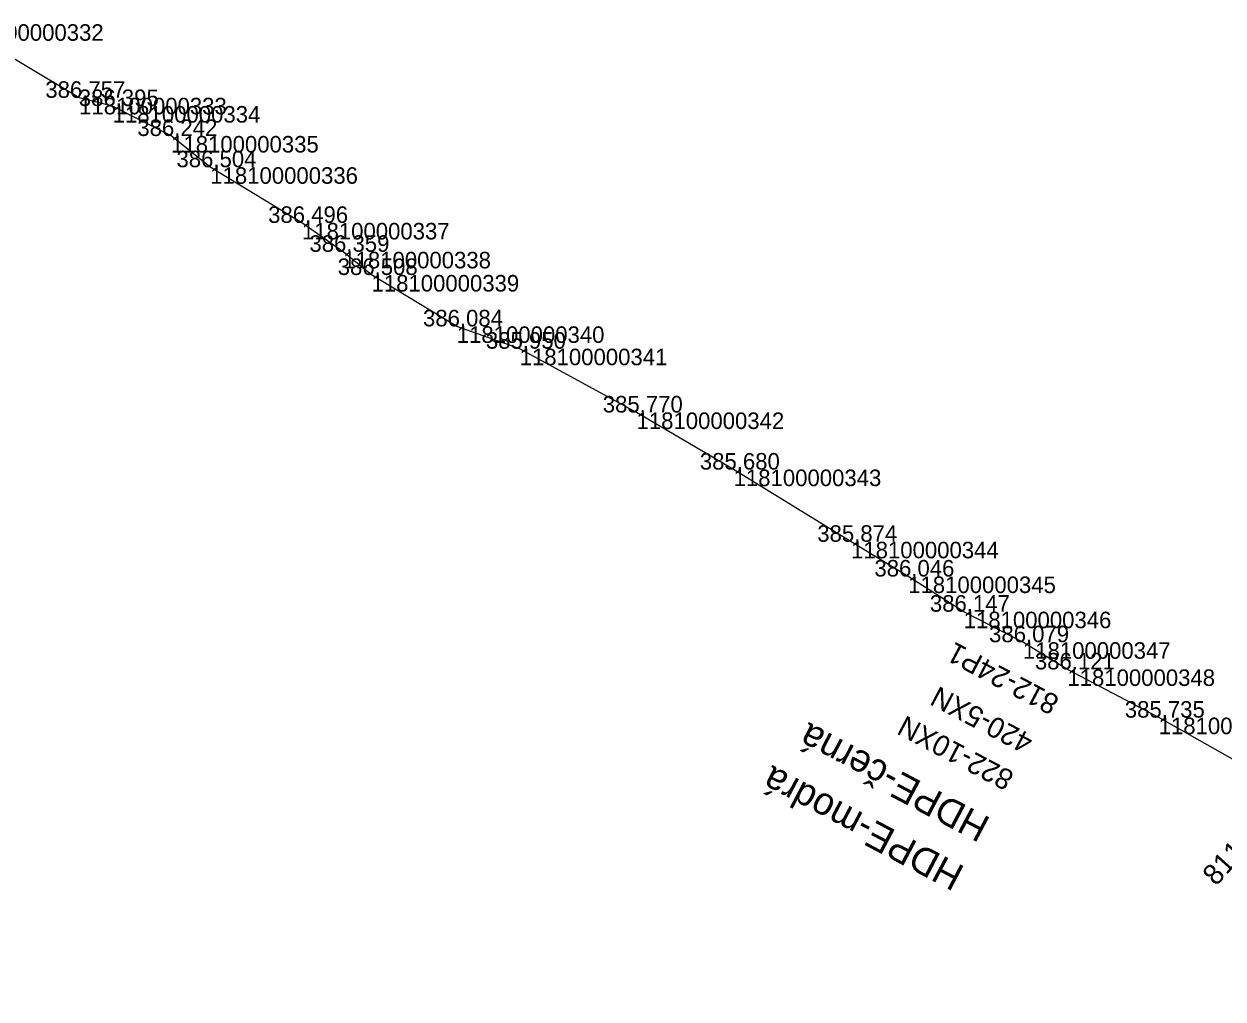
# Model space of a CAD drawing. Extents: x -724084 to -720954, y -948423 to -945131.
# Drawn here: x -721678.5 to -721591.6, y -947872.5 to -947801.8 of the extents above; entities that cross this region are included whole.
import ezdxf

# ---------------------------------------------------------------- set-up
doc = ezdxf.new("R2010")
doc.units = 0
for name, color, linetype in [('Vrstva 28', 7, 'Continuous'), ('Vrstva 31', 7, 'Continuous'), ('Vrstva 33', 7, 'Continuous'), ('Vrstva 60', 7, 'Continuous'), ('Vrstva 61', 7, 'Continuous')]:
    doc.layers.add(name, color=color, linetype=linetype)

msp = doc.modelspace()

# ---------------------------------------------------------------- linework, layer by layer
at = {"layer": 'Vrstva 28'}
msp.add_lwpolyline([(-721560.153, -947872.508), (-721568.244, -947867.917), (-721572.582, -947865.479), (-721578.506, -947861.796), (-721584.003, -947858.638), (-721589.002, -947856.173), (-721596.236, -947852.092), (-721602.857, -947848.593), (-721606.081, -947846.622), (-721610.377, -947844.405), (-721614.401, -947841.853), (-721618.546, -947839.332), (-721627.062, -947834.095), (-721634.101, -947829.952), (-721642.578, -947825.324), (-721647.14, -947823.704), (-721653.322, -947819.976), (-721655.372, -947818.295), (-721658.37, -947816.197), (-721665.018, -947812.159), (-721667.858, -947809.891), (-721672.097, -947807.719), (-721674.529, -947807.122), (-721683.459, -947801.782)], dxfattribs=at)
at = {"layer": 'Vrstva 31'}
msp.add_lwpolyline([(-721560.153, -947872.508), (-721568.244, -947867.917), (-721572.582, -947865.479), (-721578.506, -947861.796), (-721584.003, -947858.638), (-721589.002, -947856.173), (-721596.236, -947852.092), (-721602.857, -947848.593), (-721606.081, -947846.622), (-721610.377, -947844.405), (-721614.401, -947841.853), (-721618.546, -947839.332), (-721627.062, -947834.095), (-721634.101, -947829.952), (-721642.578, -947825.324), (-721647.14, -947823.704), (-721653.322, -947819.976), (-721655.372, -947818.295), (-721658.37, -947816.197), (-721665.018, -947812.159), (-721667.858, -947809.891), (-721672.097, -947807.719), (-721674.529, -947807.122), (-721683.459, -947801.782)], dxfattribs=at)
at = {"layer": 'Vrstva 33'}
msp.add_lwpolyline([(-721589.002, -947856.173), (-721596.236, -947852.092), (-721602.857, -947848.593), (-721606.081, -947846.622), (-721610.377, -947844.405), (-721614.401, -947841.853), (-721618.546, -947839.332), (-721627.062, -947834.095), (-721634.101, -947829.952), (-721642.578, -947825.324), (-721647.14, -947823.704), (-721653.322, -947819.976), (-721655.372, -947818.295), (-721658.37, -947816.197), (-721665.018, -947812.159), (-721667.858, -947809.891), (-721672.097, -947807.719), (-721674.529, -947807.122), (-721683.459, -947801.782)], dxfattribs=at)
at = {"layer": 'Vrstva 60'}
for p, q in [((-721674.529, -947807.122), (-721674.529, -947807.122)), ((-721672.097, -947807.719), (-721672.097, -947807.719)), ((-721667.858, -947809.891), (-721667.858, -947809.891)), ((-721665.018, -947812.159), (-721665.018, -947812.159)), ((-721658.37, -947816.197), (-721658.37, -947816.197)), ((-721655.372, -947818.295), (-721655.372, -947818.295)), ((-721653.322, -947819.976), (-721653.322, -947819.976)), ((-721647.14, -947823.704), (-721647.14, -947823.704)), ((-721642.578, -947825.324), (-721642.578, -947825.324)), ((-721634.101, -947829.952), (-721634.101, -947829.952)), ((-721627.062, -947834.095), (-721627.062, -947834.095)), ((-721618.546, -947839.332), (-721618.546, -947839.332)), ((-721614.401, -947841.853), (-721614.401, -947841.853)), ((-721610.377, -947844.405), (-721610.377, -947844.405)), ((-721606.081, -947846.622), (-721606.081, -947846.622)), ((-721602.857, -947848.593), (-721602.857, -947848.593)), ((-721596.236, -947852.092), (-721596.236, -947852.092))]:
    msp.add_line(p, q, dxfattribs=at)

# ---------------------------------------------------------------- texts
at = {"layer": 'Vrstva 28'}
for s, rotation, p in [('812-24P1', 152.14489, (-721603.347, -947850.629)), ('811', 47.9898, (-721592.074, -947864.367))]:
    msp.add_text(s, height=1.5, rotation=rotation, dxfattribs=at).set_placement(p)
at = {"layer": 'Vrstva 31'}
for s, p in [('420-5XN', (-721605.224, -947853.461)), ('822-10XN', (-721606.626, -947856.113))]:
    msp.add_text(s, height=1.5, rotation=152.14489, dxfattribs=at).set_placement(p)
at = {"layer": 'Vrstva 33'}
for s, p in [('HDPE-černá', (-721608.336, -947859.423)), ('HDPE-modrá', (-721610.205, -947862.959))]:
    msp.add_text(s, height=2, rotation=152.14489, dxfattribs=at).set_placement(p)
at = {"layer": 'Vrstva 60'}
for s, p in [('118100000332', (-721683.459, -947802.982)), ('118100000333', (-721674.529, -947808.322)), ('118100000334', (-721672.097, -947808.919)), ('118100000335', (-721667.858, -947811.091)), ('118100000336', (-721665.018, -947813.359)), ('118100000337', (-721658.37, -947817.397)), ('118100000338', (-721655.372, -947819.495)), ('118100000339', (-721653.322, -947821.176)), ('118100000340', (-721647.14, -947824.904)), ('118100000341', (-721642.578, -947826.524)), ('118100000342', (-721634.101, -947831.152)), ('118100000343', (-721627.062, -947835.295)), ('118100000344', (-721618.546, -947840.532)), ('118100000345', (-721614.401, -947843.053)), ('118100000346', (-721610.377, -947845.605)), ('118100000347', (-721606.081, -947847.822)), ('118100000348', (-721602.857, -947849.793)), ('118100000349', (-721596.236, -947853.292))]:
    msp.add_text(s, height=1.2, dxfattribs=at).set_placement(p)
at = {"layer": 'Vrstva 61'}
for s, p in [('386.757', (-721676.981, -947807.122)), ('386.395', (-721674.553, -947807.719)), ('386.242', (-721670.306, -947809.891)), ('386.504', (-721667.469, -947812.159)), ('386.496', (-721660.822, -947816.197)), ('386.359', (-721657.826, -947818.295)), ('386.508', (-721655.776, -947819.976)), ('386.084', (-721649.591, -947823.704)), ('385.950', (-721645.029, -947825.324)), ('385.770', (-721636.552, -947829.952)), ('385.680', (-721629.513, -947834.095)), ('385.874', (-721620.997, -947839.332)), ('386.046', (-721616.853, -947841.853)), ('386.147', (-721612.829, -947844.405)), ('386.079', (-721608.535, -947846.622)), ('386.121', (-721605.214, -947848.593)), ('385.735', (-721598.692, -947852.092))]:
    msp.add_text(s, height=1.2, dxfattribs=at).set_placement(p)

doc.saveas('drawing.dxf')
